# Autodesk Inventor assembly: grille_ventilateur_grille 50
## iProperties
Created: 2011-01
Part Number: grille_ventilateur_grille 50
Document SubType Name: Assembly
Designer: eric
Mass: 1.28275 g
Surface Area: 32.1492 cm^2
Volume: 1.28275 cm^3
Density: 1 g/cm^3
Norme de conversion: IGES 5.3
Nom du fichier: No Iges File Name specified
Préprocesseur: Autodesk Inventor 2011
Postprocesseur: Build: 342, Release: 2008 SP3 - Date: Tue 05/27/2008
Unités envoyées: MM
Incertitude: 0.01
Author: eric
